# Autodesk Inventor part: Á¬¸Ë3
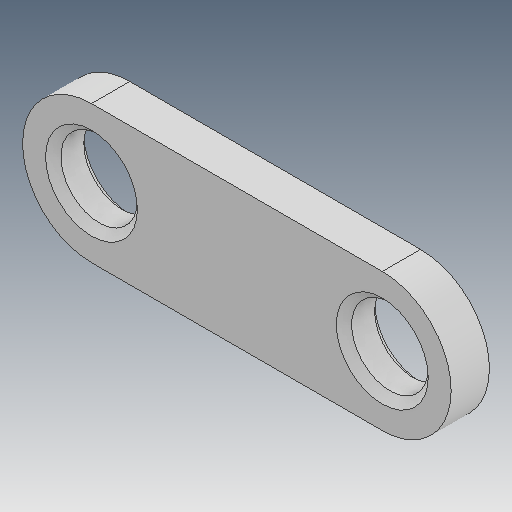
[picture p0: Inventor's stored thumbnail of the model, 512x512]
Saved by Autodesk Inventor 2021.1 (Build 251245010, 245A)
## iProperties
Created: 2015-08
Part Number: Á¬¸Ë3
Material: Ogólny
Document SubType Name: Modeling
Designer: user
Density: 1 g/cm^3
Appearance: Domyślna
Author: user
Revision Number: ÈÎºÎ
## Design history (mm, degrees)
feature "µ¹½Ç1"
node "Bryła1"
